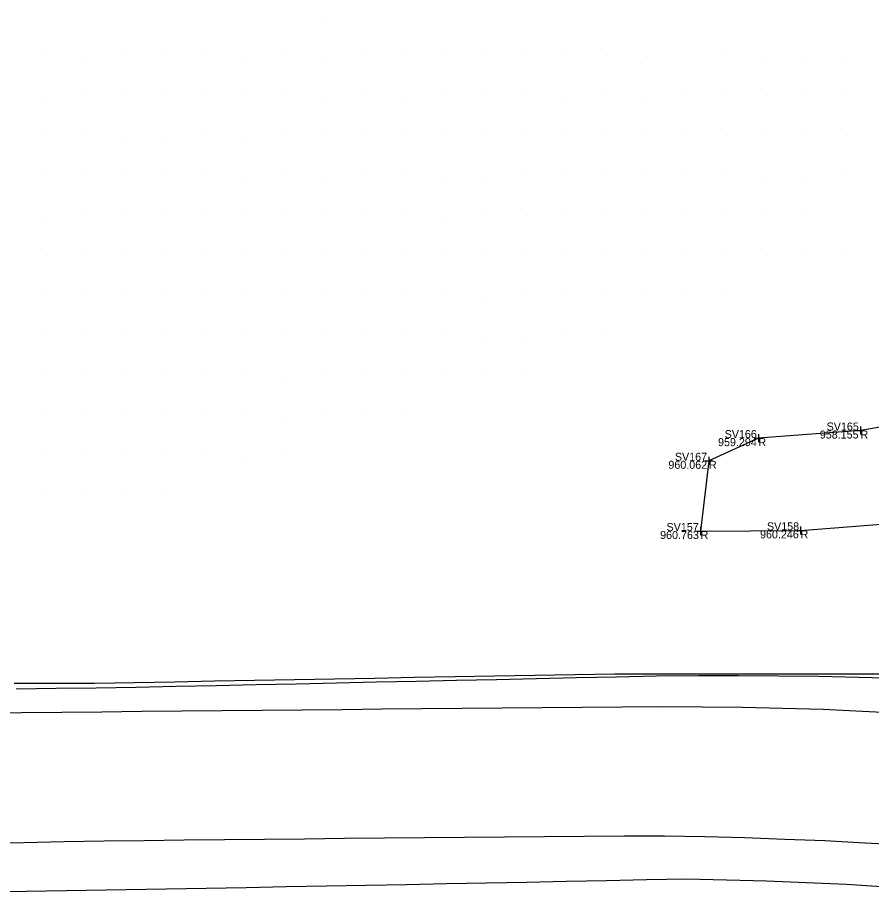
# Model space of a CAD drawing. Extents: x 2262025 to 2264532, y 740981 to 742724.
# Drawn here: x 2262814.3 to 2262920.9, y 741824.7 to 741933.8 of the extents above; entities that cross this region are included whole.
import ezdxf

# ---------------------------------------------------------------- set-up
doc = ezdxf.new("R2010")
doc.units = 0
for name, color, linetype in [('GE_X_Alignment_100_Curve_Data', 7, 'Continuous'), ('GE_X_Alignment_500_Stations', 7, 'Continuous'), ('Ground Shots', 7, 'Continuous'), ('HY_X_Spring_Cells', 7, 'Continuous'), ('RW_X_CL', 7, 'Continuous'), ('RW_X_CL_1000_Distances', 7, 'Continuous'), ('RW_X_CL_100_Cardinal_Points', 7, 'Continuous'), ('SV_X_Control_Cells_Found', 7, 'Continuous'), ('SV_X_Text_Comment', 7, 'Continuous')]:
    doc.layers.add(name, color=color, linetype=linetype)

msp = doc.modelspace()

# ---------------------------------------------------------------- linework, layer by layer
at = {"layer": 'GE_X_Alignment_100_Curve_Data'}
for points in [[(2262814.16, 741849.98), (2262819.16, 741850.04), (2262824.16, 741850.1), (2262829.15, 741850.19), (2262834.15, 741850.29), (2262839.15, 741850.4), (2262844.14, 741850.5), (2262849.14, 741850.61), (2262854.14, 741850.72), (2262859.13, 741850.83), (2262864.13, 741850.94), (2262869.12, 741851.04), (2262874.12, 741851.15), (2262879.12, 741851.26), (2262884.11, 741851.37), (2262889.11, 741851.47), (2262894.11, 741851.58), (2262899.34, 741851.65), (2262904.34, 741851.63), (2262909.34, 741851.6), (2262914.34, 741851.55), (2262919.34, 741851.42), (2262924.33, 741851.3)], [(2262812.91, 741824.65), (2262817.9, 741824.73), (2262822.9, 741824.81), (2262827.89, 741824.89), (2262832.89, 741824.98), (2262837.89, 741825.08), (2262842.88, 741825.17), (2262847.88, 741825.27), (2262852.88, 741825.36), (2262857.87, 741825.46), (2262862.87, 741825.55), (2262867.86, 741825.65), (2262872.86, 741825.74), (2262877.86, 741825.84), (2262882.85, 741825.94), (2262887.85, 741826.04), (2262892.85, 741826.14), (2262897.84, 741826.24), (2262902.84, 741826.12), (2262907.84, 741826), (2262912.83, 741825.79), (2262917.82, 741825.57), (2262922.81, 741825.25)]]:
    msp.add_lwpolyline(points, dxfattribs=at)
at = {"layer": 'GE_X_Alignment_500_Stations'}
msp.add_lwpolyline([(2262899.6, 741869.68), (2262912.08, 741869.76), (2262926.38, 741870.85), (2262938.89, 741874.62), (2262956.71, 741880.37), (2262957.78, 741885.77), (2262951.09, 741887.21), (2262940.48, 741885.76), (2262919.55, 741882.23), (2262906.81, 741881.28), (2262900.64, 741878.45)], close=True, dxfattribs=at)
at = {"layer": 'Ground Shots'}
for p, q in [((2262852.57, 741933.81), (2262852.57, 741933.81)), ((2262817.78, 741929.06), (2262817.78, 741929.06)), ((2262822.81, 741929), (2262822.81, 741929)), ((2262827.79, 741929.05), (2262827.79, 741929.05)), ((2262832.81, 741929.22), (2262832.81, 741929.22)), ((2262837.8, 741929.04), (2262837.8, 741929.04)), ((2262842.69, 741928.95), (2262842.69, 741928.95)), ((2262847.82, 741929.18), (2262847.82, 741929.18)), ((2262852.98, 741928.84), (2262852.98, 741928.84)), ((2262857.76, 741929.22), (2262857.76, 741929.22)), ((2262862.86, 741929.15), (2262862.86, 741929.15)), ((2262867.82, 741929.01), (2262867.82, 741929.01)), ((2262872.81, 741929.16), (2262872.81, 741929.16)), ((2262877.78, 741929.12), (2262877.78, 741929.12)), ((2262882.8, 741929.09), (2262882.8, 741929.09)), ((2262887.96, 741929.06), (2262887.96, 741929.06)), ((2262892.96, 741928.92), (2262892.96, 741928.92)), ((2262902.73, 741929.36), (2262902.73, 741929.36)), ((2262907.59, 741928.88), (2262907.59, 741928.88)), ((2262912.92, 741928.87), (2262912.92, 741928.87)), ((2262917.81, 741928.99), (2262917.81, 741928.99)), ((2262827.72, 741924.15), (2262827.72, 741924.15)), ((2262832.86, 741924.09), (2262832.86, 741924.09)), ((2262837.83, 741924.11), (2262837.83, 741924.11)), ((2262847.82, 741924.07), (2262847.82, 741924.07)), ((2262857.8, 741924.14), (2262857.8, 741924.14)), ((2262867.87, 741924.15), (2262867.87, 741924.15)), ((2262872.77, 741924.1), (2262872.77, 741924.1)), ((2262877.72, 741924.08), (2262877.72, 741924.08)), ((2262887.8, 741924.12), (2262887.8, 741924.12)), ((2262897.87, 741924.09), (2262897.87, 741924.09)), ((2262817.78, 741923.98), (2262817.78, 741923.98)), ((2262822.84, 741924.01), (2262822.84, 741924.01)), ((2262842.77, 741924.03), (2262842.77, 741924.03)), ((2262852.81, 741923.85), (2262852.81, 741923.85)), ((2262862.84, 741923.79), (2262862.84, 741923.79)), ((2262882.87, 741923.88), (2262882.87, 741923.88)), ((2262892.91, 741923.88), (2262892.91, 741923.88)), ((2262902.79, 741924.06), (2262902.79, 741924.06)), ((2262907.95, 741924.06), (2262907.95, 741924.06)), ((2262912.78, 741924.06), (2262912.78, 741924.06)), ((2262917.83, 741924.02), (2262917.83, 741924.02)), ((2262817.81, 741919.08), (2262817.81, 741919.08)), ((2262822.9, 741919.04), (2262822.9, 741919.04)), ((2262827.46, 741918.96), (2262827.46, 741918.96)), ((2262832.82, 741918.95), (2262832.82, 741918.95)), ((2262837.86, 741919.02), (2262837.86, 741919.02)), ((2262842.78, 741918.96), (2262842.78, 741918.96)), ((2262847.81, 741919.14), (2262847.81, 741919.14)), ((2262852.75, 741919.11), (2262852.75, 741919.11)), ((2262857.76, 741919.03), (2262857.76, 741919.03)), ((2262862.83, 741919.13), (2262862.83, 741919.13)), ((2262867.88, 741919.07), (2262867.88, 741919.07)), ((2262872.8, 741919.11), (2262872.8, 741919.11)), ((2262877.82, 741919.1), (2262877.82, 741919.1)), ((2262882.84, 741919.12), (2262882.84, 741919.12)), ((2262887.76, 741919.16), (2262887.76, 741919.16)), ((2262892.85, 741919.17), (2262892.85, 741919.17)), ((2262897.81, 741919.12), (2262897.81, 741919.12)), ((2262902.9, 741919.1), (2262902.9, 741919.1)), ((2262907.77, 741919.03), (2262907.77, 741919.03)), ((2262912.83, 741919.14), (2262912.83, 741919.14)), ((2262917.89, 741919.08), (2262917.89, 741919.08)), ((2262817.72, 741914.1), (2262817.72, 741914.1)), ((2262822.79, 741914.12), (2262822.79, 741914.12)), ((2262827.82, 741914.17), (2262827.82, 741914.17)), ((2262832.78, 741914.09), (2262832.78, 741914.09)), ((2262837.77, 741914.1), (2262837.77, 741914.1)), ((2262842.82, 741913.95), (2262842.82, 741913.95)), ((2262847.79, 741914.08), (2262847.79, 741914.08)), ((2262852.8, 741913.98), (2262852.8, 741913.98)), ((2262857.82, 741914.11), (2262857.82, 741914.11)), ((2262862.77, 741914.13), (2262862.77, 741914.13)), ((2262867.78, 741913.96), (2262867.78, 741913.96)), ((2262872.78, 741913.91), (2262872.78, 741913.91)), ((2262877.75, 741914.1), (2262877.75, 741914.1)), ((2262882.78, 741914.1), (2262882.78, 741914.1)), ((2262887.85, 741914.14), (2262887.85, 741914.14)), ((2262892.85, 741914.09), (2262892.85, 741914.09)), ((2262897.85, 741914.18), (2262897.85, 741914.18)), ((2262902.81, 741914.07), (2262902.81, 741914.07)), ((2262907.75, 741913.95), (2262907.75, 741913.95)), ((2262912.8, 741913.92), (2262912.8, 741913.92)), ((2262917.77, 741914.1), (2262917.77, 741914.1)), ((2262817.87, 741909.01), (2262817.87, 741909.01)), ((2262822.76, 741909.13), (2262822.76, 741909.13)), ((2262827.81, 741909.14), (2262827.81, 741909.14)), ((2262832.79, 741909.1), (2262832.79, 741909.1)), ((2262837.81, 741909.06), (2262837.81, 741909.06)), ((2262842.81, 741909.16), (2262842.81, 741909.16)), ((2262847.83, 741909.18), (2262847.83, 741909.18)), ((2262852.84, 741909.04), (2262852.84, 741909.04)), ((2262857.78, 741909.12), (2262857.78, 741909.12)), ((2262862.83, 741909.16), (2262862.83, 741909.16)), ((2262867.76, 741908.88), (2262867.76, 741908.88)), ((2262872.77, 741909.09), (2262872.77, 741909.09)), ((2262877.94, 741909.08), (2262877.94, 741909.08)), ((2262882.79, 741909.17), (2262882.79, 741909.17)), ((2262887.77, 741909.12), (2262887.77, 741909.12)), ((2262892.83, 741909.12), (2262892.83, 741909.12)), ((2262897.8, 741909.11), (2262897.8, 741909.11)), ((2262902.8, 741909.08), (2262902.8, 741909.08)), ((2262907.79, 741909.12), (2262907.79, 741909.12)), ((2262912.79, 741909.07), (2262912.79, 741909.07)), ((2262818.01, 741904.08), (2262818.01, 741904.08)), ((2262822.81, 741904.18), (2262822.81, 741904.18)), ((2262827.79, 741904.17), (2262827.79, 741904.17)), ((2262832.82, 741904.11), (2262832.82, 741904.11)), ((2262837.83, 741904.1), (2262837.83, 741904.1)), ((2262842.82, 741904.14), (2262842.82, 741904.14)), ((2262847.88, 741904.1), (2262847.88, 741904.1)), ((2262852.8, 741904.16), (2262852.8, 741904.16)), ((2262857.82, 741904.09), (2262857.82, 741904.09)), ((2262862.75, 741904.12), (2262862.75, 741904.12)), ((2262867.85, 741904.06), (2262867.85, 741904.06)), ((2262872.78, 741904.09), (2262872.78, 741904.09)), ((2262877.84, 741904.12), (2262877.84, 741904.12)), ((2262882.82, 741904.15), (2262882.82, 741904.15)), ((2262887.77, 741904.1), (2262887.77, 741904.1)), ((2262892.83, 741904.19), (2262892.83, 741904.19)), ((2262897.81, 741904.19), (2262897.81, 741904.19)), ((2262902.82, 741904.12), (2262902.82, 741904.12)), ((2262907.89, 741904.08), (2262907.89, 741904.08)), ((2262912.82, 741904.15), (2262912.82, 741904.15)), ((2262917.75, 741904.12), (2262917.75, 741904.12)), ((2262817.8, 741899.11), (2262817.8, 741899.11)), ((2262822.83, 741899.12), (2262822.83, 741899.12)), ((2262827.75, 741899.12), (2262827.75, 741899.12)), ((2262832.76, 741899.13), (2262832.76, 741899.13)), ((2262837.82, 741899.15), (2262837.82, 741899.15)), ((2262842.83, 741899.1), (2262842.83, 741899.1)), ((2262847.83, 741899.09), (2262847.83, 741899.09)), ((2262852.83, 741899.17), (2262852.83, 741899.17)), ((2262857.8, 741899.11), (2262857.8, 741899.11)), ((2262862.78, 741899.2), (2262862.78, 741899.2)), ((2262867.79, 741899.12), (2262867.79, 741899.12)), ((2262872.83, 741899), (2262872.83, 741899)), ((2262877.79, 741899.11), (2262877.79, 741899.11)), ((2262882.84, 741899.14), (2262882.84, 741899.14)), ((2262887.79, 741899.12), (2262887.79, 741899.12)), ((2262892.84, 741899.08), (2262892.84, 741899.08)), ((2262897.86, 741899.04), (2262897.86, 741899.04)), ((2262902.82, 741899.06), (2262902.82, 741899.06)), ((2262817.81, 741894.08), (2262817.81, 741894.08)), ((2262822.8, 741894.13), (2262822.8, 741894.13)), ((2262827.84, 741894.06), (2262827.84, 741894.06)), ((2262832.78, 741894.13), (2262832.78, 741894.13)), ((2262837.83, 741894.04), (2262837.83, 741894.04)), ((2262842.79, 741894.08), (2262842.79, 741894.08)), ((2262847.82, 741894.1), (2262847.82, 741894.1)), ((2262852.83, 741894.2), (2262852.83, 741894.2)), ((2262857.8, 741894.13), (2262857.8, 741894.13)), ((2262862.75, 741894.24), (2262862.75, 741894.24)), ((2262867.82, 741894.06), (2262867.82, 741894.06)), ((2262872.56, 741893.85), (2262872.56, 741893.85)), ((2262877.8, 741893.98), (2262877.8, 741893.98)), ((2262882.73, 741894.13), (2262882.73, 741894.13)), ((2262887.65, 741894.13), (2262887.65, 741894.13)), ((2262857.85, 741889.18), (2262857.85, 741889.18)), ((2262867.8, 741889.15), (2262867.8, 741889.15)), ((2262877.69, 741889.52), (2262877.69, 741889.52)), ((2262817.81, 741889.11), (2262817.81, 741889.11)), ((2262822.8, 741889.13), (2262822.8, 741889.13)), ((2262827.81, 741889.09), (2262827.81, 741889.09)), ((2262832.87, 741889.1), (2262832.87, 741889.1)), ((2262837.8, 741889.04), (2262837.8, 741889.04)), ((2262842.83, 741889.09), (2262842.83, 741889.09)), ((2262847.78, 741889.03), (2262847.78, 741889.03)), ((2262852.75, 741889.11), (2262852.75, 741889.11)), ((2262862.8, 741889.13), (2262862.8, 741889.13)), ((2262872.78, 741889.08), (2262872.78, 741889.08)), ((2262817.76, 741884.16), (2262817.76, 741884.16)), ((2262822.79, 741884.12), (2262822.79, 741884.12)), ((2262827.84, 741884.07), (2262827.84, 741884.07)), ((2262832.8, 741884.09), (2262832.8, 741884.09)), ((2262837.78, 741884.15), (2262837.78, 741884.15)), ((2262842.73, 741884.14), (2262842.73, 741884.14)), ((2262847.86, 741884.04), (2262847.86, 741884.04)), ((2262852.81, 741884.12), (2262852.81, 741884.12)), ((2262857.74, 741884.5), (2262857.74, 741884.5)), ((2262862.74, 741884.43), (2262862.74, 741884.43)), ((2262817.8, 741879.1), (2262817.8, 741879.1)), ((2262822.83, 741879.11), (2262822.83, 741879.11)), ((2262827.83, 741879.11), (2262827.83, 741879.11)), ((2262832.89, 741879.12), (2262832.89, 741879.12)), ((2262837.81, 741879.09), (2262837.81, 741879.09)), ((2262842.67, 741878.96), (2262842.67, 741878.96)), ((2262847.72, 741879.22), (2262847.72, 741879.22)), ((2262817.8, 741874.14), (2262817.8, 741874.14)), ((2262822.79, 741874.13), (2262822.79, 741874.13)), ((2262827.82, 741874.09), (2262827.82, 741874.09)), ((2262832.8, 741874.2), (2262832.8, 741874.2))]:
    msp.add_line(p, q, dxfattribs=at)
at = {"layer": 'RW_X_CL_1000_Distances'}
for points in [[(2262809.87, 741846.95), (2262814.87, 741847.01), (2262819.86, 741847.06), (2262824.86, 741847.11), (2262829.86, 741847.16), (2262834.86, 741847.21), (2262839.85, 741847.25), (2262844.85, 741847.3), (2262849.85, 741847.35), (2262854.85, 741847.4), (2262859.84, 741847.45), (2262864.84, 741847.5), (2262869.84, 741847.55), (2262874.83, 741847.59), (2262879.83, 741847.64), (2262884.83, 741847.69), (2262889.82, 741847.72), (2262894.82, 741847.76), (2262899.82, 741847.71), (2262904.81, 741847.66), (2262909.81, 741847.55), (2262914.91, 741847.43), (2262919.8, 741847.17), (2262924.79, 741846.91)], [(2262925.08, 741830.44), (2262920.09, 741830.71), (2262915.09, 741830.97), (2262910.1, 741831.16), (2262905.11, 741831.34), (2262900.11, 741831.47), (2262895.11, 741831.57), (2262890.12, 741831.56), (2262885.12, 741831.54), (2262880.12, 741831.5), (2262875.13, 741831.46), (2262870.13, 741831.41), (2262865.13, 741831.36), (2262860.14, 741831.31), (2262855.14, 741831.26), (2262850.14, 741831.21), (2262845.14, 741831.16), (2262840.15, 741831.11), (2262835.15, 741831.05), (2262830.15, 741831), (2262825.16, 741830.94), (2262820.16, 741830.85), (2262815.17, 741830.75), (2262810.17, 741830.66)]]:
    msp.add_lwpolyline(points, dxfattribs=at)
at = {"layer": 'RW_X_CL_100_Cardinal_Points'}
for p, q in [((2262919.55, 741882.73), (2262919.55, 741881.73)), ((2262906.81, 741881.78), (2262906.81, 741880.78)), ((2262919.05, 741882.23), (2262920.05, 741882.23)), ((2262919.55, 741882.23), (2262919.55, 741882.23)), ((2262906.31, 741881.28), (2262907.31, 741881.28)), ((2262906.81, 741881.28), (2262906.81, 741881.28)), ((2262900.14, 741878.45), (2262901.14, 741878.45)), ((2262900.64, 741878.95), (2262900.64, 741877.95)), ((2262900.64, 741878.45), (2262900.64, 741878.45)), ((2262899.1, 741869.68), (2262900.1, 741869.68)), ((2262899.6, 741870.18), (2262899.6, 741869.18)), ((2262899.6, 741869.68), (2262899.6, 741869.68)), ((2262911.58, 741869.76), (2262912.58, 741869.76)), ((2262912.08, 741870.26), (2262912.08, 741869.26)), ((2262912.08, 741869.76), (2262912.08, 741869.76))]:
    msp.add_line(p, q, dxfattribs=at)
at = {"layer": 'SV_X_Control_Cells_Found'}
msp.add_lwpolyline([(2262813.93, 741850.67), (2262818.93, 741850.67), (2262823.93, 741850.69), (2262828.93, 741850.77), (2262833.92, 741850.86), (2262838.92, 741850.95), (2262843.91, 741851.04), (2262848.91, 741851.13), (2262853.91, 741851.22), (2262858.9, 741851.31), (2262863.9, 741851.41), (2262868.9, 741851.5), (2262873.89, 741851.59), (2262878.89, 741851.68), (2262883.89, 741851.77), (2262888.88, 741851.84), (2262893.88, 741851.85), (2262898.88, 741851.85), (2262903.88, 741851.85), (2262908.87, 741851.85), (2262913.87, 741851.85), (2262918.87, 741851.85), (2262923.87, 741851.85)], dxfattribs=at)

# ---------------------------------------------------------------- texts
at = {"layer": 'HY_X_Spring_Cells'}
for s, p in [('958.155', (2262914.48, 741881.23)), ('959.294', (2262901.78, 741880.28)), ('960.062', (2262895.58, 741877.45)), ('960.763', (2262894.55, 741868.68)), ('960.246', (2262907.02, 741868.76))]:
    msp.add_text(s, height=1, dxfattribs=at).set_placement(p)
at = {"layer": 'RW_X_CL'}
for p in [(2262919.55, 741881.23), (2262906.81, 741880.28), (2262900.64, 741877.45), (2262899.6, 741868.68), (2262912.08, 741868.76)]:
    msp.add_text('R', height=1, dxfattribs=at).set_placement(p)
at = {"layer": 'SV_X_Text_Comment'}
for s, p in [('SV165', (2262915.33, 741882.23)), ('SV166', (2262902.6, 741881.28)), ('SV167', (2262896.39, 741878.45)), ('SV157', (2262895.35, 741869.68)), ('SV158', (2262907.88, 741869.76))]:
    msp.add_text(s, height=1, dxfattribs=at).set_placement(p)

doc.saveas('drawing.dxf')
